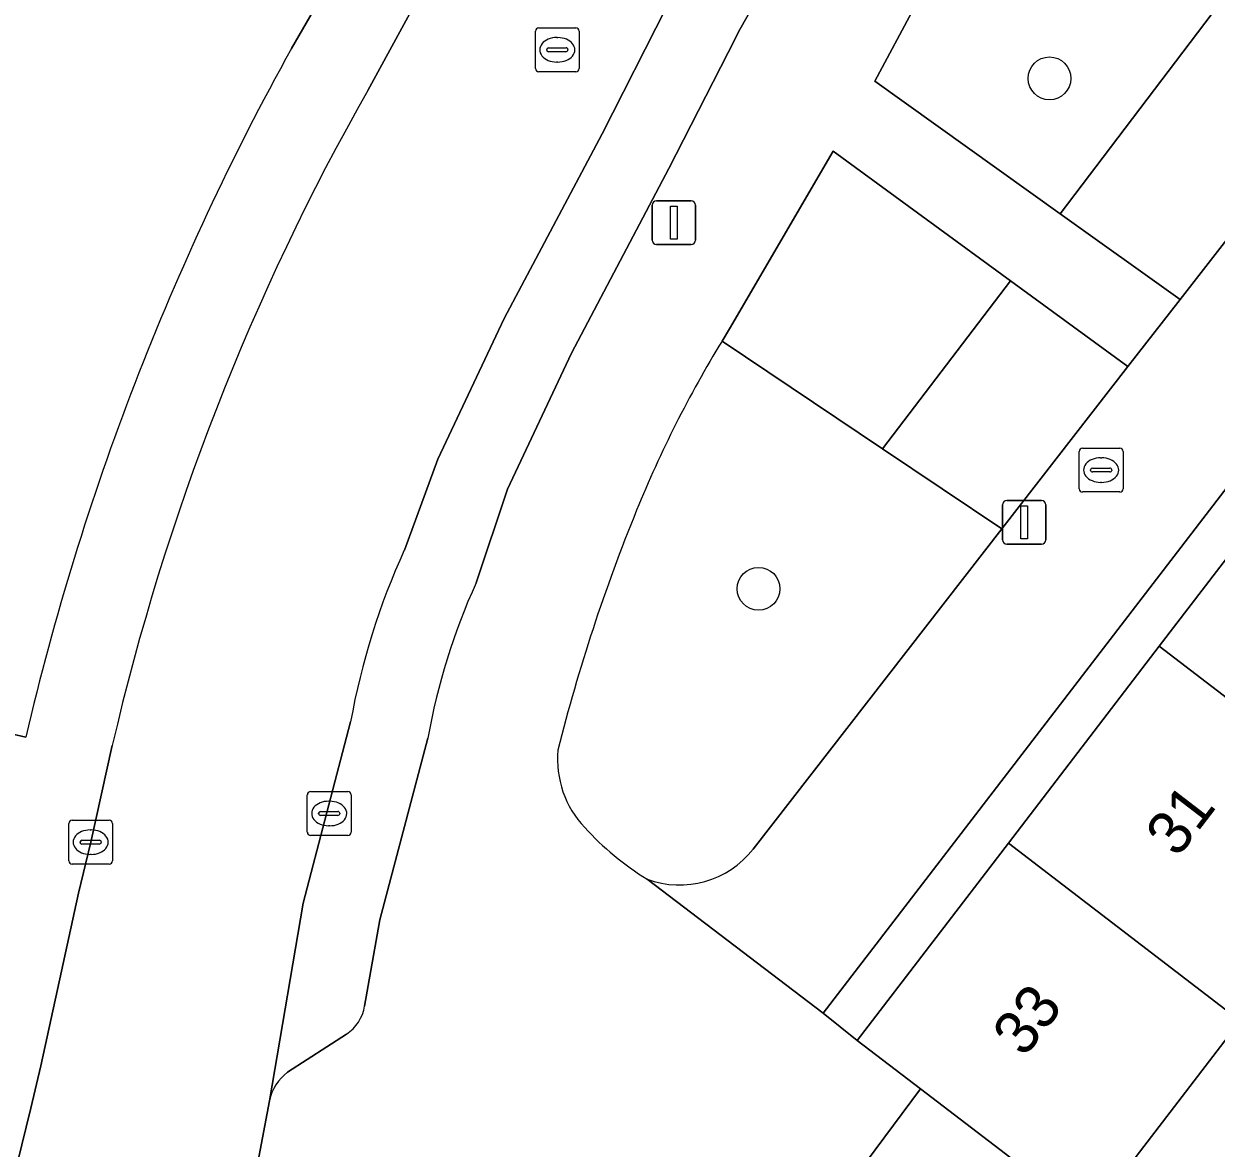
# Model space of a CAD drawing. Extents: x 159039 to 160102, y 381214 to 382524.
# Drawn here: x 159209.5 to 159236.73, y 381573.94 to 381599.62 of the extents above; entities that cross this region are included whole.
import ezdxf

# ---------------------------------------------------------------- set-up
doc = ezdxf.new("R2010")
doc.units = 0
for name, color, linetype in [('IMGEO_Boom', 7, 'Continuous'), ('IMGEO_Erf', 7, 'Continuous'), ('IMGEO_Groenvoorziening', 7, 'Continuous'), ('IMGEO_Kolk', 7, 'Continuous'), ('IMGEO_Lichtmast', 7, 'Continuous'), ('IMGEO_Pand', 7, 'Continuous'), ('IMGEO_Pand_nummerreeks', 7, 'Continuous'), ('IMGEO_Parkeervlak_open', 7, 'Continuous'), ('IMGEO_Rijbaan_lokaal_open', 7, 'Continuous'), ('IMGEO_Rioolput', 7, 'Continuous'), ('IMGEO_Voetpad_open', 7, 'Continuous')]:
    doc.layers.add(name, color=color, linetype=linetype)

msp = doc.modelspace()

# ---------------------------------------------------------------- linework, layer by layer
at = {"layer": 'IMGEO_Boom'}
for centre in [(159232.921, 381598.377), (159226.276, 381586.719)]:
    msp.add_circle(centre, 0.489, dxfattribs=at)
at = {"layer": 'IMGEO_Erf'}
for points in [[(159262.015, 381621.636), (159227.754, 381577.026), (159228.532, 381576.406), (159231.983, 381580.909), (159235.43, 381585.407), (159238.851, 381589.872)], [(159237.276, 381576.854), (159233.825, 381572.35), (159229.978, 381575.298), (159226.645, 381570.82)]]:
    msp.add_lwpolyline(points, dxfattribs=at)
at = {"layer": 'IMGEO_Groenvoorziening'}
for points in [[(159233.169, 381595.283), (159245.71, 381611.823), (159239.336, 381616.675), (159229.836, 381600.002), (159228.936, 381598.311)], [(159233.169, 381595.283), (159235.905, 381593.326), (159241.102, 381600.002), (159248.591, 381609.63), (159245.71, 381611.823)], [(159229.11, 381589.916), (159232.032, 381593.755), (159227.977, 381596.716), (159225.612, 381592.653), (159225.442, 381592.378)], [(159231.833, 381588.088), (159234.714, 381591.797), (159232.032, 381593.755), (159229.11, 381589.916)]]:
    msp.add_lwpolyline(points, close=True, dxfattribs=at)
for points in [[(159215.61, 381599.061), (159217.597, 381602.497), (159214.846, 381603.954), (159198.911, 381596.28), (159193.268, 381593.562), (159202.354, 381574.906), (159202.503, 381574.358), (159204.406, 381582.55), (159202.55, 381582.967), (159202.367, 381583.018), (159202.788, 381584.972), (159206.836, 381583.949), (159209.539, 381583.329)], [(159226.151, 381580.771), (159231.833, 381588.088), (159229.11, 381589.916), (159225.442, 381592.378)]]:
    msp.add_lwpolyline(points, dxfattribs=at)
for centre, radius, start, end in [((159268.907, 381569.456), 60.967, 150.9492, 166.84746), ((159248.422, 381578.362), 26.917, 148.6204, 157.847), ((159261.064, 381573.137), 40.596, 157.7449, 165.8881), ((159223.964, 381582.829), 2.28, 174.8281, 223.3189), ((159227.142, 381585.671), 6.542, 222.3303, 238.5899), ((159224.472, 381582.088), 2.134, 249.7003, 321.8774)]:
    msp.add_arc(centre, radius, start, end, dxfattribs=at)
at = {"layer": 'IMGEO_Kolk'}
for p, q in [((159216.045, 381582.087), (159216.897, 381582.087)), ((159215.97, 381581.161), (159215.97, 381582.013)), ((159216.458, 381581.867), (159216.483, 381581.867)), ((159216.971, 381582.013), (159216.971, 381581.161)), ((159216.229, 381581.581), (159216.229, 381581.593)), ((159216.667, 381581.544), (159216.269, 381581.544)), ((159216.272, 381581.63), (159216.67, 381581.63)), ((159216.713, 381581.593), (159216.713, 381581.581)), ((159210.521, 381580.506), (159210.521, 381581.358)), ((159210.596, 381581.432), (159211.448, 381581.432)), ((159211.009, 381581.212), (159211.034, 381581.212)), ((159211.522, 381581.358), (159211.522, 381580.506)), ((159216.481, 381581.307), (159216.456, 381581.307)), ((159210.78, 381580.926), (159210.78, 381580.938)), ((159210.823, 381580.975), (159211.221, 381580.975)), ((159211.264, 381580.938), (159211.264, 381580.926)), ((159216.897, 381581.087), (159216.045, 381581.087)), ((159211.218, 381580.889), (159210.82, 381580.889)), ((159211.032, 381580.652), (159211.007, 381580.652)), ((159211.448, 381580.432), (159210.596, 381580.432))]:
    msp.add_line(p, q, dxfattribs=at)
for points in [[(159216.045, 381582.087), (159216.897, 381582.087)], [(159215.97, 381581.161), (159215.97, 381582.013)], [(159216.971, 381582.013), (159216.971, 381581.161)], [(159210.521, 381580.506), (159210.521, 381581.358)], [(159210.596, 381581.432), (159211.448, 381581.432)], [(159211.522, 381581.358), (159211.522, 381580.506)], [(159216.897, 381581.087), (159216.045, 381581.087)], [(159211.448, 381580.432), (159210.596, 381580.432)]]:
    msp.add_lwpolyline(points, dxfattribs=at)
for centre, radius, start, end in [((159216.047, 381582.011), 0.0765, 91.552, 178.448), ((159216.047, 381582.011), 0.0765, 91.552, 178.448), ((159216.895, 381582.011), 0.0765, 1.552, 88.448), ((159216.895, 381582.011), 0.0765, 1.552, 88.448), ((159216.269, 381581.59), 0.0403, 85.8775, 175.7526), ((159216.266, 381581.58), 0.0366, 178.938, 274.7102), ((159216.67, 381581.587), 0.043, 264.8664, 352.4533), ((159216.674, 381581.592), 0.0386, 1.7309, 96.639), ((159210.598, 381581.356), 0.0765, 91.552, 178.448), ((159210.598, 381581.356), 0.0765, 91.552, 178.448), ((159211.446, 381581.356), 0.0765, 1.552, 88.448), ((159211.446, 381581.356), 0.0765, 1.552, 88.448), ((159210.82, 381580.935), 0.0403, 85.8775, 175.7526), ((159210.817, 381580.925), 0.0366, 178.938, 274.7102), ((159211.221, 381580.932), 0.043, 264.8664, 352.4533), ((159211.225, 381580.937), 0.0386, 1.7309, 96.639), ((159216.047, 381581.163), 0.0765, 181.552, 268.448), ((159216.047, 381581.163), 0.0765, 181.552, 268.448), ((159216.895, 381581.163), 0.0765, 271.552, 358.448), ((159216.895, 381581.163), 0.0765, 271.552, 358.448), ((159210.598, 381580.508), 0.0765, 181.552, 268.448), ((159210.598, 381580.508), 0.0765, 181.552, 268.448), ((159211.446, 381580.508), 0.0765, 271.552, 358.448), ((159211.446, 381580.508), 0.0765, 271.552, 358.448)]:
    msp.add_arc(centre, radius, start, end, dxfattribs=at)
for centre, major_axis, ratio, start_param, end_param in [((159216.457, 381581.587), (-0.387, 0.002), 0.722429, 4.712389, 7.853982), ((159216.482, 381581.587), (-0.39, 0.002), 0.717154, 1.570796, 4.712389), ((159211.008, 381580.932), (-0.387, 0.002), 0.722429, 4.712389, 7.853982), ((159211.033, 381580.932), (-0.39, 0.002), 0.717154, 1.570796, 4.712389)]:
    msp.add_ellipse(centre, major_axis=major_axis, ratio=ratio, start_param=start_param, end_param=end_param, dxfattribs=at)
at = {"layer": 'IMGEO_Lichtmast'}
for p, q in [((159223.846, 381594.68), (159223.846, 381595.48)), ((159223.846, 381595.48), (159223.846, 381594.68)), ((159223.946, 381595.58), (159224.736, 381595.58)), ((159224.736, 381595.58), (159223.946, 381595.58)), ((159224.836, 381595.48), (159224.836, 381594.68)), ((159224.836, 381594.68), (159224.836, 381595.48)), ((159224.736, 381594.58), (159223.946, 381594.58)), ((159223.946, 381594.58), (159224.736, 381594.58)), ((159231.85, 381587.838), (159231.85, 381588.638)), ((159231.85, 381588.638), (159231.85, 381587.838)), ((159231.95, 381588.738), (159232.74, 381588.738)), ((159232.74, 381588.738), (159231.95, 381588.738)), ((159232.84, 381588.638), (159232.84, 381587.838)), ((159232.84, 381587.838), (159232.84, 381588.638)), ((159232.74, 381587.738), (159231.95, 381587.738)), ((159231.95, 381587.738), (159232.74, 381587.738))]:
    msp.add_line(p, q, dxfattribs=at)
for points in [[(159224.266, 381595.455), (159224.416, 381595.455), (159224.416, 381594.705), (159224.266, 381594.705), (159224.266, 381595.455)], [(159232.27, 381588.613), (159232.42, 381588.613), (159232.42, 381587.863), (159232.27, 381587.863), (159232.27, 381588.613)]]:
    msp.add_lwpolyline(points, dxfattribs=at)
for centre, start, end in [((159223.946, 381595.48), 90, 180), ((159223.946, 381595.48), 90, 180), ((159224.736, 381595.48), 0, 90), ((159224.736, 381595.48), 360, 90), ((159223.946, 381594.68), 180, 270), ((159223.946, 381594.68), 180, 270), ((159224.736, 381594.68), 270, 0), ((159224.736, 381594.68), 270, 0), ((159231.95, 381588.638), 90, 180), ((159231.95, 381588.638), 90, 180), ((159232.74, 381588.638), 0, 90), ((159232.74, 381588.638), 360, 90), ((159231.95, 381587.838), 180, 270), ((159231.95, 381587.838), 180, 270), ((159232.74, 381587.838), 270, 0), ((159232.74, 381587.838), 270, 0)]:
    msp.add_arc(centre, 0.1, start, end, dxfattribs=at)
at = {"layer": 'IMGEO_Pand'}
for points in [[(159240.723, 381581.352), (159244.145, 381585.817), (159238.851, 381589.872), (159235.43, 381585.407)], [(159240.723, 381581.352), (159235.43, 381585.407), (159231.983, 381580.909), (159237.276, 381576.854)], [(159231.983, 381580.909), (159228.532, 381576.406), (159229.978, 381575.298), (159233.825, 381572.35), (159237.276, 381576.854)]]:
    msp.add_lwpolyline(points, close=True, dxfattribs=at)
at = {"layer": 'IMGEO_Parkeervlak_open'}
for points in [[(159245.452, 381634.739), (159244.834, 381636.136), (159244.844, 381636.563), (159241.619, 381630.72), (159228.291, 381607.288), (159226.937, 381604.907), (159224.275, 381600.226), (159224.174, 381600.002), (159222.703, 381597.111), (159220.463, 381592.89), (159218.951, 381589.678), (159218.186, 381587.604)], [(159219.827, 381586.854), (159220.544, 381588.995), (159222.004, 381592.098), (159224.228, 381596.316), (159225.749, 381599.292), (159225.817, 381599.442), (159243.126, 381629.875)], [(159216.959, 381583.682), (159215.878, 381579.537), (159215.105, 381575.027)], [(159217.278, 381577.19), (159217.624, 381579.158), (159218.724, 381583.304)], [(159215.52, 381575.676), (159216.864, 381576.546)]]:
    msp.add_lwpolyline(points, dxfattribs=at)
for centre, radius, start, end in [((159233.337, 381580.711), 16.646, 155.537, 169.7183), ((159233.335, 381580.711), 14.84, 155.5444, 169.9351), ((159216.344, 381577.335), 0.945, 303.3714, 351.1581), ((159216.154, 381574.814), 1.07, 126.3102, 168.4965)]:
    msp.add_arc(centre, radius, start, end, dxfattribs=at)
at = {"layer": 'IMGEO_Rijbaan_lokaal_open'}
for points in [[(159218.186, 381587.604), (159218.951, 381589.678), (159220.463, 381592.89), (159222.703, 381597.111), (159224.174, 381600.002), (159224.275, 381600.226), (159226.937, 381604.907), (159222.581, 381607.401), (159219.493, 381602.004), (159219.373, 381601.81), (159217.353, 381598.102)], [(159214.627, 381572.488), (159215.105, 381575.027), (159215.878, 381579.537), (159216.959, 381583.682)], [(159211.516, 381583.139), (159211.024, 381580.932), (159210.747, 381579.765), (159210.264, 381577.571), (159209.883, 381575.825), (159209.653, 381574.858), (159208.927, 381571.913)]]:
    msp.add_lwpolyline(points, dxfattribs=at)
for centre, radius, start, end in [((159265.954, 381570.523), 55.881, 150.427, 166.952), ((159233.337, 381580.711), 16.646, 155.537, 169.7183)]:
    msp.add_arc(centre, radius, start, end, dxfattribs=at)
at = {"layer": 'IMGEO_Rioolput'}
for p, q in [((159221.179, 381598.603), (159221.179, 381599.455)), ((159221.254, 381599.529), (159222.106, 381599.529)), ((159222.18, 381599.455), (159222.18, 381598.603)), ((159221.667, 381599.309), (159221.692, 381599.309)), ((159221.438, 381599.023), (159221.438, 381599.035)), ((159221.876, 381598.986), (159221.478, 381598.986)), ((159221.481, 381599.072), (159221.879, 381599.072)), ((159221.922, 381599.035), (159221.922, 381599.023)), ((159221.69, 381598.749), (159221.665, 381598.749)), ((159222.106, 381598.529), (159221.254, 381598.529)), ((159233.676, 381589.93), (159234.528, 381589.93)), ((159233.601, 381589.004), (159233.601, 381589.856)), ((159234.089, 381589.71), (159234.114, 381589.71)), ((159234.602, 381589.856), (159234.602, 381589.004)), ((159233.86, 381589.424), (159233.86, 381589.436)), ((159234.298, 381589.387), (159233.9, 381589.387)), ((159233.903, 381589.473), (159234.301, 381589.473)), ((159234.344, 381589.436), (159234.344, 381589.424)), ((159234.112, 381589.15), (159234.087, 381589.15)), ((159234.528, 381588.93), (159233.676, 381588.93))]:
    msp.add_line(p, q, dxfattribs=at)
for points in [[(159221.179, 381598.603), (159221.179, 381599.455)], [(159221.254, 381599.529), (159222.106, 381599.529)], [(159222.18, 381599.455), (159222.18, 381598.603)], [(159222.106, 381598.529), (159221.254, 381598.529)], [(159233.676, 381589.93), (159234.528, 381589.93)], [(159233.601, 381589.004), (159233.601, 381589.856)], [(159234.602, 381589.856), (159234.602, 381589.004)], [(159234.528, 381588.93), (159233.676, 381588.93)]]:
    msp.add_lwpolyline(points, dxfattribs=at)
for centre, radius, start, end in [((159221.256, 381599.453), 0.0765, 91.552, 178.448), ((159221.256, 381599.453), 0.0765, 91.552, 178.448), ((159222.104, 381599.453), 0.0765, 1.552, 88.448), ((159222.104, 381599.453), 0.0765, 1.552, 88.448), ((159221.478, 381599.032), 0.0403, 85.8775, 175.7526), ((159221.475, 381599.022), 0.0366, 178.938, 274.7102), ((159221.879, 381599.029), 0.043, 264.8664, 352.4533), ((159221.883, 381599.034), 0.0386, 1.7309, 96.639), ((159221.256, 381598.605), 0.0765, 181.552, 268.448), ((159221.256, 381598.605), 0.0765, 181.552, 268.448), ((159222.104, 381598.605), 0.0765, 271.552, 358.448), ((159222.104, 381598.605), 0.0765, 271.552, 358.448), ((159233.678, 381589.854), 0.0765, 91.552, 178.448), ((159233.678, 381589.854), 0.0765, 91.552, 178.448), ((159234.526, 381589.854), 0.0765, 1.552, 88.448), ((159234.526, 381589.854), 0.0765, 1.552, 88.448), ((159233.9, 381589.433), 0.0403, 85.8775, 175.7526), ((159233.897, 381589.423), 0.0366, 178.938, 274.7102), ((159234.301, 381589.43), 0.043, 264.8664, 352.4533), ((159234.305, 381589.435), 0.0386, 1.7309, 96.639), ((159233.678, 381589.006), 0.0765, 181.552, 268.448), ((159233.678, 381589.006), 0.0765, 181.552, 268.448), ((159234.526, 381589.006), 0.0765, 271.552, 358.448), ((159234.526, 381589.006), 0.0765, 271.552, 358.448)]:
    msp.add_arc(centre, radius, start, end, dxfattribs=at)
for centre, major_axis, ratio, start_param, end_param in [((159221.666, 381599.029), (-0.387, 0.002), 0.722429, 4.712389, 7.853982), ((159221.691, 381599.029), (-0.39, 0.002), 0.717154, 1.570796, 4.712389), ((159234.088, 381589.43), (-0.387, 0.002), 0.722429, 4.712389, 7.853982), ((159234.113, 381589.43), (-0.39, 0.002), 0.717154, 1.570796, 4.712389)]:
    msp.add_ellipse(centre, major_axis=major_axis, ratio=ratio, start_param=start_param, end_param=end_param, dxfattribs=at)
at = {"layer": 'IMGEO_Voetpad_open'}
for points in [[(159225.442, 381592.378), (159225.612, 381592.653), (159227.977, 381596.716), (159232.032, 381593.755), (159234.714, 381591.797), (159235.905, 381593.326), (159233.169, 381595.283), (159228.936, 381598.311), (159229.836, 381600.002), (159239.336, 381616.675), (159245.71, 381611.823), (159248.591, 381609.63), (159249.573, 381610.904), (159246.793, 381613.04), (159240.167, 381618.131), (159246.583, 381629.452), (159247.797, 381631.594), (159250.607, 381636.319), (159251.425, 381637.759), (159252.243, 381639.199), (159252.767, 381638.853), (159254.798, 381637.51)], [(159245.421, 381634.028), (159243.126, 381629.875), (159225.817, 381599.442), (159225.749, 381599.292), (159224.228, 381596.316), (159222.004, 381592.098), (159220.544, 381588.995), (159219.827, 381586.854)], [(159259.818, 381624.187), (159257.927, 381621.736), (159249.573, 381610.904), (159248.591, 381609.63), (159241.102, 381600.002), (159235.905, 381593.326), (159234.714, 381591.797), (159231.833, 381588.088), (159226.151, 381580.771)], [(159223.732, 381580.087), (159227.754, 381577.026), (159262.015, 381621.636)], [(159217.353, 381598.102), (159219.373, 381601.81), (159219.493, 381602.004), (159222.581, 381607.401), (159222.91, 381607.955), (159223.223, 381608.545), (159223.559, 381609.178), (159221.857, 381610.145), (159220.977, 381608.522), (159220.836, 381608.145), (159218.381, 381603.872), (159217.597, 381602.497), (159215.61, 381599.061)], [(159209.539, 381583.329), (159206.836, 381583.949), (159206.389, 381581.973), (159209.094, 381581.331), (159208.162, 381577.105), (159207.664, 381575.044), (159206.596, 381570.536), (159203.881, 381571.269), (159203.208, 381568.394), (159203.358, 381568.043), (159203.097, 381567.92), (159203.072, 381567.908), (159202.865, 381568.336), (159200.943, 381567.422), (159201.133, 381567.05), (159202.311, 381564.566), (159202.427, 381564.333), (159204.23, 381563.566), (159202.211, 381559.115), (159197.939, 381551.409)], [(159208.927, 381571.913), (159209.653, 381574.858), (159209.883, 381575.825), (159210.264, 381577.571), (159210.747, 381579.765), (159211.024, 381580.932), (159211.516, 381583.139)], [(159218.724, 381583.304), (159217.624, 381579.158), (159217.278, 381577.19)], [(159215.105, 381575.027), (159214.627, 381572.488), (159220.263, 381570.498), (159220.823, 381570.074), (159224.279, 381567.641), (159226.645, 381570.82), (159229.978, 381575.298), (159228.532, 381576.406), (159227.754, 381577.026), (159223.732, 381580.087)], [(159216.864, 381576.546), (159215.52, 381575.676)]]:
    msp.add_lwpolyline(points, dxfattribs=at)
for centre, radius, start, end in [((159268.907, 381569.456), 60.967, 150.9492, 166.84746), ((159265.954, 381570.523), 55.881, 150.427, 166.952), ((159248.422, 381578.362), 26.917, 148.6204, 157.847), ((159261.064, 381573.137), 40.596, 157.7449, 165.8881), ((159233.335, 381580.711), 14.84, 155.5444, 169.9351), ((159223.964, 381582.829), 2.28, 174.8281, 223.3189), ((159227.142, 381585.671), 6.542, 222.3303, 238.5899), ((159224.472, 381582.088), 2.134, 249.7003, 321.8774), ((159216.344, 381577.335), 0.945, 303.3714, 351.1581), ((159216.154, 381574.814), 1.07, 126.3102, 168.4965)]:
    msp.add_arc(centre, radius, start, end, dxfattribs=at)

# ---------------------------------------------------------------- texts
at = {"layer": 'IMGEO_Pand_nummerreeks'}
for s, p in [('31', (159235.844, 381580.554)), ('33', (159232.347, 381575.992))]:
    msp.add_text(s, height=1, rotation=52.5374, dxfattribs=at).set_placement(p)

doc.saveas('drawing.dxf')
